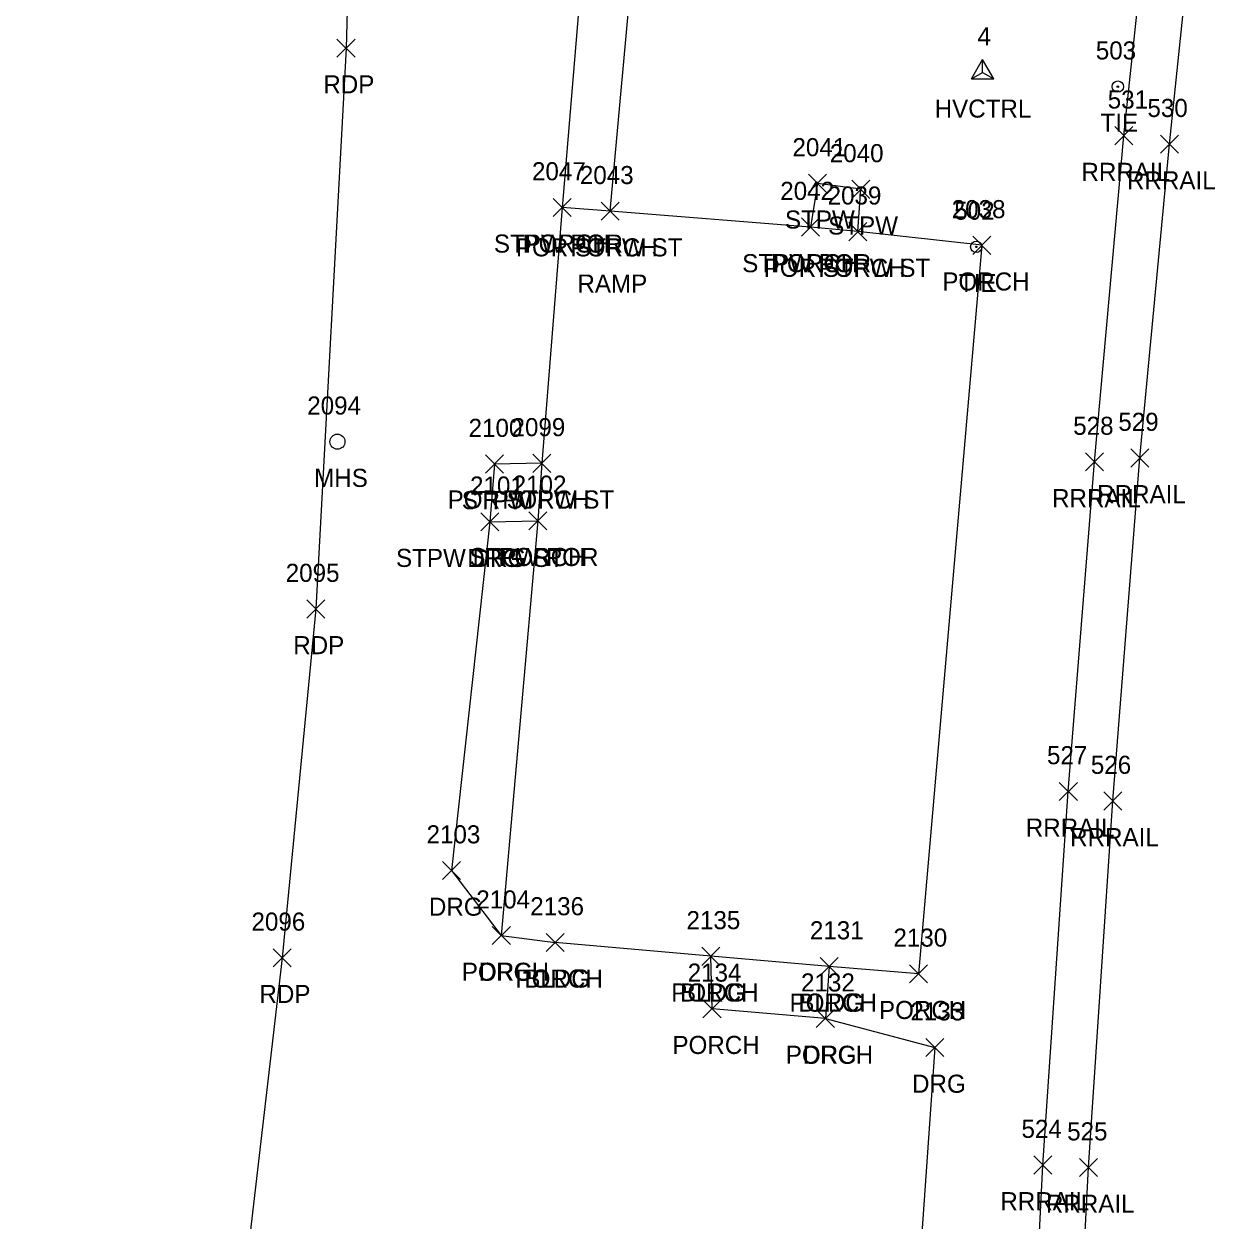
# Model space of a CAD drawing. Extents: x 1767353 to 1772625, y 740790 to 747702.
# Drawn here: x 1770045.2 to 1770179.1, y 741538.9 to 741671.2 of the extents above; entities that cross this region are included whole.
import ezdxf

# ---------------------------------------------------------------- set-up
doc = ezdxf.new("R2010")
doc.units = 0
for name, color, linetype in [('C_A', 7, 'Continuous'), ('C_I', 7, 'Continuous'), ('CBP', 7, 'Continuous'), ('CPSM', 7, 'Continuous'), ('L_A', 7, 'Continuous'), ('L_C', 7, 'Continuous'), ('L_I', 7, 'Continuous'), ('L_TIC', 7, 'Continuous'), ('LBC', 7, 'Continuous'), ('LBF', 7, 'Continuous'), ('P_A', 7, 'Continuous'), ('P_I', 7, 'Continuous'), ('P_TIC', 7, 'Continuous'), ('PET', 7, 'Continuous'), ('R_A', 7, 'Continuous'), ('R_I', 7, 'Continuous'), ('R_TIC', 7, 'Continuous'), ('RDG', 7, 'Continuous'), ('RR', 7, 'Continuous'), ('U_A', 7, 'Continuous'), ('U_I', 7, 'Continuous'), ('USMH', 7, 'Continuous')]:
    doc.layers.add(name, color=color, linetype=linetype)

msp = doc.modelspace()

# ---------------------------------------------------------------- linework, layer by layer
at = {"layer": 'CBP'}
for centre, radius in [((1770166.17, 741664.33), 0.625), ((1770166.17, 741664.33), 0.0833), ((1770150.51, 741646.61), 0.625), ((1770150.51, 741646.61), 0.0833)]:
    msp.add_circle(centre, radius, dxfattribs=at)
at = {"layer": 'CPSM'}
for p, q in [((1770149.96, 741665.18), (1770151.21, 741667.34)), ((1770149.96, 741665.18), (1770151.21, 741667.34)), ((1770149.96, 741665.18), (1770151.21, 741667.34)), ((1770149.96, 741665.18), (1770151.21, 741667.34)), ((1770149.96, 741665.18), (1770151.21, 741667.34)), ((1770149.96, 741665.18), (1770151.21, 741667.34)), ((1770149.96, 741665.18), (1770151.21, 741667.34)), ((1770149.96, 741665.18), (1770151.21, 741667.34)), ((1770149.96, 741665.18), (1770151.21, 741667.34)), ((1770149.96, 741665.18), (1770151.21, 741667.34)), ((1770152.46, 741665.18), (1770151.21, 741667.34)), ((1770151.21, 741665.9), (1770151.21, 741667.34)), ((1770152.46, 741665.18), (1770151.21, 741667.34)), ((1770151.21, 741665.9), (1770151.21, 741667.34)), ((1770152.46, 741665.18), (1770151.21, 741667.34)), ((1770151.21, 741665.9), (1770151.21, 741667.34)), ((1770152.46, 741665.18), (1770151.21, 741667.34)), ((1770151.21, 741665.9), (1770151.21, 741667.34)), ((1770152.46, 741665.18), (1770151.21, 741667.34)), ((1770151.21, 741665.9), (1770151.21, 741667.34)), ((1770152.46, 741665.18), (1770151.21, 741667.34)), ((1770151.21, 741665.9), (1770151.21, 741667.34)), ((1770152.46, 741665.18), (1770151.21, 741667.34)), ((1770151.21, 741665.9), (1770151.21, 741667.34)), ((1770152.46, 741665.18), (1770151.21, 741667.34)), ((1770151.21, 741665.9), (1770151.21, 741667.34)), ((1770152.46, 741665.18), (1770151.21, 741667.34)), ((1770151.21, 741665.9), (1770151.21, 741667.34)), ((1770152.46, 741665.18), (1770151.21, 741667.34)), ((1770151.21, 741665.9), (1770151.21, 741667.34)), ((1770149.96, 741665.18), (1770151.21, 741665.9)), ((1770149.96, 741665.18), (1770151.21, 741665.9)), ((1770149.96, 741665.18), (1770151.21, 741665.9)), ((1770149.96, 741665.18), (1770151.21, 741665.9)), ((1770149.96, 741665.18), (1770151.21, 741665.9)), ((1770149.96, 741665.18), (1770151.21, 741665.9)), ((1770149.96, 741665.18), (1770151.21, 741665.9)), ((1770149.96, 741665.18), (1770151.21, 741665.9)), ((1770149.96, 741665.18), (1770151.21, 741665.9)), ((1770149.96, 741665.18), (1770151.21, 741665.9)), ((1770149.96, 741665.18), (1770152.46, 741665.18)), ((1770149.96, 741665.18), (1770152.46, 741665.18)), ((1770149.96, 741665.18), (1770152.46, 741665.18)), ((1770149.96, 741665.18), (1770152.46, 741665.18)), ((1770149.96, 741665.18), (1770152.46, 741665.18)), ((1770149.96, 741665.18), (1770152.46, 741665.18)), ((1770149.96, 741665.18), (1770152.46, 741665.18)), ((1770149.96, 741665.18), (1770152.46, 741665.18)), ((1770149.96, 741665.18), (1770152.46, 741665.18)), ((1770149.96, 741665.18), (1770152.46, 741665.18)), ((1770151.21, 741665.9), (1770151.21, 741665.9)), ((1770151.21, 741665.9), (1770152.46, 741665.18)), ((1770151.21, 741665.9), (1770151.21, 741665.9)), ((1770151.21, 741665.9), (1770152.46, 741665.18)), ((1770151.21, 741665.9), (1770151.21, 741665.9)), ((1770151.21, 741665.9), (1770152.46, 741665.18)), ((1770151.21, 741665.9), (1770151.21, 741665.9)), ((1770151.21, 741665.9), (1770152.46, 741665.18)), ((1770151.21, 741665.9), (1770151.21, 741665.9)), ((1770151.21, 741665.9), (1770152.46, 741665.18)), ((1770151.21, 741665.9), (1770151.21, 741665.9)), ((1770151.21, 741665.9), (1770152.46, 741665.18)), ((1770151.21, 741665.9), (1770151.21, 741665.9)), ((1770151.21, 741665.9), (1770152.46, 741665.18)), ((1770151.21, 741665.9), (1770151.21, 741665.9)), ((1770151.21, 741665.9), (1770152.46, 741665.18)), ((1770151.21, 741665.9), (1770151.21, 741665.9)), ((1770151.21, 741665.9), (1770152.46, 741665.18)), ((1770151.21, 741665.9), (1770151.21, 741665.9)), ((1770151.21, 741665.9), (1770152.46, 741665.18))]:
    msp.add_line(p, q, dxfattribs=at)
at = {"layer": 'L_TIC'}
for points in [[(1770131.94, 741652.63), (1770133.94, 741654.63)], [(1770133.94, 741652.63), (1770131.94, 741654.63)], [(1770136.73, 741651.97), (1770138.73, 741653.97)], [(1770138.73, 741651.97), (1770136.73, 741653.97)], [(1770103.69, 741649.97), (1770105.69, 741651.97)], [(1770105.69, 741649.97), (1770103.69, 741651.97)], [(1770103.69, 741649.97), (1770105.69, 741651.97)], [(1770105.69, 741649.97), (1770103.69, 741651.97)], [(1770108.99, 741649.55), (1770110.99, 741651.55)], [(1770110.99, 741649.55), (1770108.99, 741651.55)], [(1770108.99, 741649.55), (1770110.99, 741651.55)], [(1770110.99, 741649.55), (1770108.99, 741651.55)], [(1770131.16, 741647.8), (1770133.16, 741649.8)], [(1770133.16, 741647.8), (1770131.16, 741649.8)], [(1770131.16, 741647.8), (1770133.16, 741649.8)], [(1770133.16, 741647.8), (1770131.16, 741649.8)], [(1770136.41, 741647.29), (1770138.41, 741649.29)], [(1770138.41, 741647.29), (1770136.41, 741649.29)], [(1770136.41, 741647.29), (1770138.41, 741649.29)], [(1770138.41, 741647.29), (1770136.41, 741649.29)], [(1770150.12, 741645.78), (1770152.12, 741647.78)], [(1770152.12, 741645.78), (1770150.12, 741647.78)], [(1770150.12, 741645.78), (1770152.12, 741647.78)], [(1770152.12, 741645.78), (1770150.12, 741647.78)], [(1770096.2, 741621.59), (1770098.2, 741623.59)], [(1770098.2, 741621.59), (1770096.2, 741623.59)], [(1770101.43, 741621.67), (1770103.43, 741623.67)], [(1770103.43, 741621.67), (1770101.43, 741623.67)], [(1770101.43, 741621.67), (1770103.43, 741623.67)], [(1770103.43, 741621.67), (1770101.43, 741623.67)], [(1770095.7, 741615.21), (1770097.7, 741617.21)], [(1770097.7, 741615.21), (1770095.7, 741617.21)], [(1770100.99, 741615.31), (1770102.99, 741617.31)], [(1770102.99, 741615.31), (1770100.99, 741617.31)], [(1770100.99, 741615.31), (1770102.99, 741617.31)], [(1770102.99, 741615.31), (1770100.99, 741617.31)], [(1770096.96, 741569.44), (1770098.96, 741571.44)], [(1770098.96, 741569.44), (1770096.96, 741571.44)], [(1770102.91, 741568.69), (1770104.91, 741570.69)], [(1770104.91, 741568.69), (1770102.91, 741570.69)], [(1770102.91, 741568.69), (1770104.91, 741570.69)], [(1770104.91, 741568.69), (1770102.91, 741570.69)], [(1770120.14, 741567.15), (1770122.14, 741569.15)], [(1770122.14, 741567.15), (1770120.14, 741569.15)], [(1770120.14, 741567.15), (1770122.14, 741569.15)], [(1770122.14, 741567.15), (1770120.14, 741569.15)], [(1770133.23, 741566.03), (1770135.23, 741568.03)], [(1770135.23, 741566.03), (1770133.23, 741568.03)], [(1770133.23, 741566.03), (1770135.23, 741568.03)], [(1770135.23, 741566.03), (1770133.23, 741568.03)], [(1770143.11, 741565.22), (1770145.11, 741567.22)], [(1770145.11, 741565.22), (1770143.11, 741567.22)], [(1770120.27, 741561.35), (1770122.27, 741563.35)], [(1770122.27, 741561.35), (1770120.27, 741563.35)], [(1770132.81, 741560.26), (1770134.81, 741562.26)], [(1770134.81, 741560.26), (1770132.81, 741562.26)]]:
    msp.add_lwpolyline(points, dxfattribs=at)
at = {"layer": 'LBC'}
msp.add_lwpolyline([(1770134.23, 741567.03), (1770121.14, 741568.15), (1770103.91, 741569.69)], dxfattribs=at)
at = {"layer": 'LBF'}
for points in [[(1770109.99, 741650.55), (1770112.66, 741679.69), (1770107.13, 741680.16), (1770104.69, 741650.97)], [(1770137.41, 741648.29), (1770137.73, 741652.97), (1770132.94, 741653.63), (1770132.16, 741648.8)], [(1770151.12, 741646.78), (1770137.41, 741648.29), (1770132.16, 741648.8), (1770109.99, 741650.55), (1770104.69, 741650.97), (1770102.43, 741622.67), (1770101.99, 741616.31), (1770097.96, 741570.44), (1770103.91, 741569.69)], [(1770151.12, 741646.78), (1770144.11, 741566.22), (1770134.23, 741567.03), (1770133.81, 741561.26), (1770121.27, 741562.35), (1770121.14, 741568.15)], [(1770102.43, 741622.67), (1770097.2, 741622.59), (1770096.7, 741616.21), (1770101.99, 741616.31)]]:
    msp.add_lwpolyline(points, dxfattribs=at)
at = {"layer": 'P_TIC'}
for points in [[(1770079.78, 741667.58), (1770081.78, 741669.58)], [(1770081.78, 741667.58), (1770079.78, 741669.58)], [(1770076.45, 741605.56), (1770078.45, 741607.56)], [(1770078.45, 741605.56), (1770076.45, 741607.56)], [(1770072.71, 741566.99), (1770074.71, 741568.99)], [(1770074.71, 741566.99), (1770072.71, 741568.99)]]:
    msp.add_lwpolyline(points, dxfattribs=at)
at = {"layer": 'PET'}
msp.add_lwpolyline([(1770086.36, 741896.23), (1770087.49, 741787.65), (1770087.53, 741783.15), (1770087.13, 741775.79), (1770085.91, 741755.24), (1770081.77, 741704.72), (1770080.78, 741668.58), (1770077.45, 741606.56), (1770073.71, 741567.99), (1770067.82, 741517.29), (1770065.02, 741495.1), (1770064.65, 741473.85), (1770058.3, 741423.48), (1770050.58, 741368.28), (1770045.18, 741323.67)], dxfattribs=at)
at = {"layer": 'R_TIC'}
for points in [[(1770165.84, 741657.9), (1770167.84, 741659.9)], [(1770167.84, 741657.9), (1770165.84, 741659.9)], [(1770170.89, 741656.97), (1770172.89, 741658.97)], [(1770172.89, 741656.97), (1770170.89, 741658.97)], [(1770162.59, 741621.82), (1770164.59, 741623.82)], [(1770164.59, 741621.82), (1770162.59, 741623.82)], [(1770167.59, 741622.26), (1770169.59, 741624.26)], [(1770169.59, 741622.26), (1770167.59, 741624.26)], [(1770095.7, 741615.21), (1770097.7, 741617.21)], [(1770097.7, 741615.21), (1770095.7, 741617.21)], [(1770159.69, 741585.39), (1770161.69, 741587.39)], [(1770161.69, 741585.39), (1770159.69, 741587.39)], [(1770164.6, 741584.33), (1770166.6, 741586.33)], [(1770166.6, 741584.33), (1770164.6, 741586.33)], [(1770091.46, 741576.64), (1770093.46, 741578.64)], [(1770093.46, 741576.64), (1770091.46, 741578.64)], [(1770096.96, 741569.44), (1770098.96, 741571.44)], [(1770098.96, 741569.44), (1770096.96, 741571.44)], [(1770132.81, 741560.26), (1770134.81, 741562.26)], [(1770134.81, 741560.26), (1770132.81, 741562.26)], [(1770144.92, 741557.06), (1770146.92, 741559.06)], [(1770146.92, 741557.06), (1770144.92, 741559.06)], [(1770156.87, 741544.07), (1770158.87, 741546.07)], [(1770158.87, 741544.07), (1770156.87, 741546.07)], [(1770161.92, 741543.79), (1770163.92, 741545.79)], [(1770163.92, 741543.79), (1770161.92, 741545.79)]]:
    msp.add_lwpolyline(points, dxfattribs=at)
at = {"layer": 'RDG'}
for points in [[(1770096.7, 741616.21), (1770092.46, 741577.64), (1770097.96, 741570.44)], [(1770133.81, 741561.26), (1770145.92, 741558.06), (1770141.18, 741490.11), (1770127.23, 741468.75), (1770075.49, 741475.78), (1770072.87, 741474.48), (1770072.05, 741472.61)]]:
    msp.add_lwpolyline(points, dxfattribs=at)
at = {"layer": 'RR'}
for points in [[(1770158.18, 741192.17), (1770156.33, 741234.55), (1770154.66, 741279.77), (1770153.5, 741326.69), (1770153.07, 741379.82), (1770153.42, 741422.94), (1770154.43, 741466.02), (1770156.03, 741508.16), (1770157.87, 741545.07), (1770160.69, 741586.39), (1770163.59, 741622.82), (1770166.84, 741658.9), (1770171.01, 741697.88), (1770175.49, 741734.8), (1770180.59, 741775.05), (1770185.91, 741810.5), (1770192.47, 741851.32), (1770197.89, 741882.78), (1770201.13, 741901.96), (1770208.66, 741941.8), (1770211.54, 741956.24), (1770217.02, 741983.21), (1770222.11, 742006.18)], [(1770163.08, 741192.31), (1770161.21, 741234.64), (1770159.62, 741280.6), (1770158.4, 741326.37), (1770158.03, 741379.87), (1770158.37, 741422.76), (1770159.48, 741466.41), (1770160.97, 741507.07), (1770162.92, 741544.79), (1770165.6, 741585.33), (1770168.59, 741623.26), (1770171.89, 741657.97), (1770175.98, 741697.29), (1770180.38, 741733.87), (1770185.58, 741774.59), (1770190.55, 741808.84), (1770197.31, 741850.84), (1770202.43, 741880.83), (1770205.99, 741900.79), (1770213.55, 741940.61), (1770216.39, 741955.4), (1770221.78, 741982.04), (1770226.9, 742005.14)]]:
    msp.add_lwpolyline(points, dxfattribs=at)
at = {"layer": 'USMH'}
for p, q in [((1770079.83, 741625.06), (1770079.83, 741625.06)), ((1770080.66, 741625.06), (1770080.66, 741625.06))]:
    msp.add_line(p, q, dxfattribs=at)
msp.add_circle((1770079.83, 741625.06), 0.833, dxfattribs=at)

# ---------------------------------------------------------------- texts
at = {"layer": 'C_A'}
for s, p in [('HVCTRL', (1770145.9, 741660.9)), ('HVCTRL', (1770145.9, 741660.9)), ('HVCTRL', (1770145.9, 741660.9)), ('HVCTRL', (1770145.9, 741660.9)), ('HVCTRL', (1770145.9, 741660.9)), ('HVCTRL', (1770145.9, 741660.9)), ('HVCTRL', (1770145.9, 741660.9)), ('HVCTRL', (1770145.9, 741660.9)), ('HVCTRL', (1770145.9, 741660.9)), ('HVCTRL', (1770145.9, 741660.9)), ('TIE', (1770164.25, 741659.33)), ('TIE', (1770148.59, 741641.61))]:
    msp.add_text(s, height=2, dxfattribs=at).set_placement(p)
at = {"layer": 'C_I'}
for s, p in [('4', (1770150.64, 741668.9)), ('4', (1770150.64, 741668.9)), ('4', (1770150.64, 741668.9)), ('4', (1770150.64, 741668.9)), ('4', (1770150.64, 741668.9)), ('4', (1770150.64, 741668.9)), ('4', (1770150.64, 741668.9)), ('4', (1770150.64, 741668.9)), ('4', (1770150.64, 741668.9)), ('4', (1770150.64, 741668.9)), ('503', (1770163.73, 741667.33)), ('502', (1770148.07, 741649.61))]:
    msp.add_text(s, height=2, dxfattribs=at).set_placement(p)
at = {"layer": 'L_A'}
for s, p in [('STPW', (1770129.34, 741648.63)), ('STPW', (1770134.12, 741647.97)), ('STPW POR', (1770097.14, 741645.97)), ('POR STPW ST', (1770099.57, 741645.55)), ('PORCH', (1770100.31, 741645.97)), ('PORCH', (1770105.61, 741645.55)), ('STPW POR', (1770124.61, 741643.8)), ('POR STPW ST', (1770126.99, 741643.29)), ('PORCH', (1770127.78, 741643.8)), ('PORCH', (1770133.03, 741643.29)), ('PORCH', (1770146.75, 741641.78)), ('PORCH', (1770146.75, 741641.78)), ('POR STPW ST', (1770092.02, 741617.67)), ('STPW', (1770093.59, 741617.59)), ('PORCH', (1770098.06, 741617.67)), ('STPW DRG ST', (1770086.31, 741611.21)), ('STPW POR', (1770094.44, 741611.31)), ('PORCH', (1770097.62, 741611.31)), ('PORCH', (1770093.59, 741565.44)), ('PORCH', (1770099.53, 741564.69)), ('BLDG', (1770100.5, 741564.69)), ('PORCH', (1770116.76, 741563.15)), ('BLDG', (1770117.73, 741563.15)), ('PORCH', (1770129.85, 741562.03)), ('BLDG', (1770130.82, 741562.03)), ('PORCH', (1770139.74, 741561.22)), ('PORCH', (1770116.89, 741557.35)), ('PORCH', (1770129.43, 741556.26))]:
    msp.add_text(s, height=2, dxfattribs=at).set_placement(p)
at = {"layer": 'L_C'}
msp.add_text('RAMP', height=2, dxfattribs=at).set_placement((1770106.38, 741641.55))
at = {"layer": 'L_I'}
for s, p in [('2041', (1770130.17, 741656.63)), ('2040', (1770134.3, 741655.97)), ('2047', (1770101.35, 741653.97)), ('2047', (1770101.35, 741653.97)), ('2043', (1770106.65, 741653.55)), ('2043', (1770106.65, 741653.55)), ('2042', (1770128.82, 741651.8)), ('2042', (1770128.82, 741651.8)), ('2039', (1770134.06, 741651.29)), ('2039', (1770134.06, 741651.29)), ('2038', (1770147.79, 741649.78)), ('2038', (1770147.79, 741649.78)), ('2100', (1770094.34, 741625.59)), ('2099', (1770099.09, 741625.67)), ('2099', (1770099.09, 741625.67)), ('2101', (1770094.5, 741619.21)), ('2102', (1770099.22, 741619.31)), ('2102', (1770099.22, 741619.31)), ('2104', (1770095.19, 741573.44)), ('2136', (1770101.16, 741572.69)), ('2136', (1770101.16, 741572.69)), ('2135', (1770118.45, 741571.15)), ('2135', (1770118.45, 741571.15)), ('2131', (1770132.1, 741570.03)), ('2131', (1770132.1, 741570.03)), ('2130', (1770141.34, 741569.22)), ('2134', (1770118.58, 741565.35)), ('2132', (1770131.12, 741564.26))]:
    msp.add_text(s, height=2, dxfattribs=at).set_placement(p)
at = {"layer": 'P_A'}
for p in [(1770078.27, 741663.58), (1770074.94, 741601.56), (1770071.2, 741562.99)]:
    msp.add_text('RDP', height=2, dxfattribs=at).set_placement(p)
at = {"layer": 'P_I'}
for s, p in [('2095', (1770074.11, 741609.56)), ('2096', (1770070.32, 741570.99))]:
    msp.add_text(s, height=2, dxfattribs=at).set_placement(p)
at = {"layer": 'R_A'}
for s, p in [('RRRAIL', (1770162.14, 741653.9)), ('RRRAIL', (1770167.18, 741652.97)), ('RRRAIL', (1770158.89, 741617.82)), ('RRRAIL', (1770163.88, 741618.26)), ('DRG', (1770094.19, 741611.21)), ('RRRAIL', (1770155.98, 741581.39)), ('RRRAIL', (1770160.89, 741580.33)), ('DRG', (1770089.95, 741572.64)), ('DRG', (1770095.45, 741565.44)), ('DRG', (1770131.3, 741556.26)), ('DRG', (1770143.4, 741553.06)), ('RRRAIL', (1770153.17, 741540.07)), ('RRRAIL', (1770158.21, 741539.79))]:
    msp.add_text(s, height=2, dxfattribs=at).set_placement(p)
at = {"layer": 'R_I'}
for s, p in [('531', (1770165.05, 741661.9)), ('530', (1770169.44, 741660.97)), ('528', (1770161.23, 741625.82)), ('529', (1770166.22, 741626.26)), ('2101', (1770094.5, 741619.21)), ('527', (1770158.33, 741589.39)), ('526', (1770163.18, 741588.33)), ('2103', (1770089.69, 741580.64)), ('2104', (1770095.19, 741573.44)), ('2132', (1770131.12, 741564.26)), ('2133', (1770143.22, 741561.06)), ('524', (1770155.51, 741548.07)), ('525', (1770160.56, 741547.79))]:
    msp.add_text(s, height=2, dxfattribs=at).set_placement(p)
at = {"layer": 'U_A'}
msp.add_text('MHS', height=2, dxfattribs=at).set_placement((1770077.25, 741620.06))
at = {"layer": 'U_I'}
msp.add_text('2094', height=2, dxfattribs=at).set_placement((1770076.49, 741628.06))

doc.saveas('drawing.dxf')
